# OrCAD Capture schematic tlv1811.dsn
size A
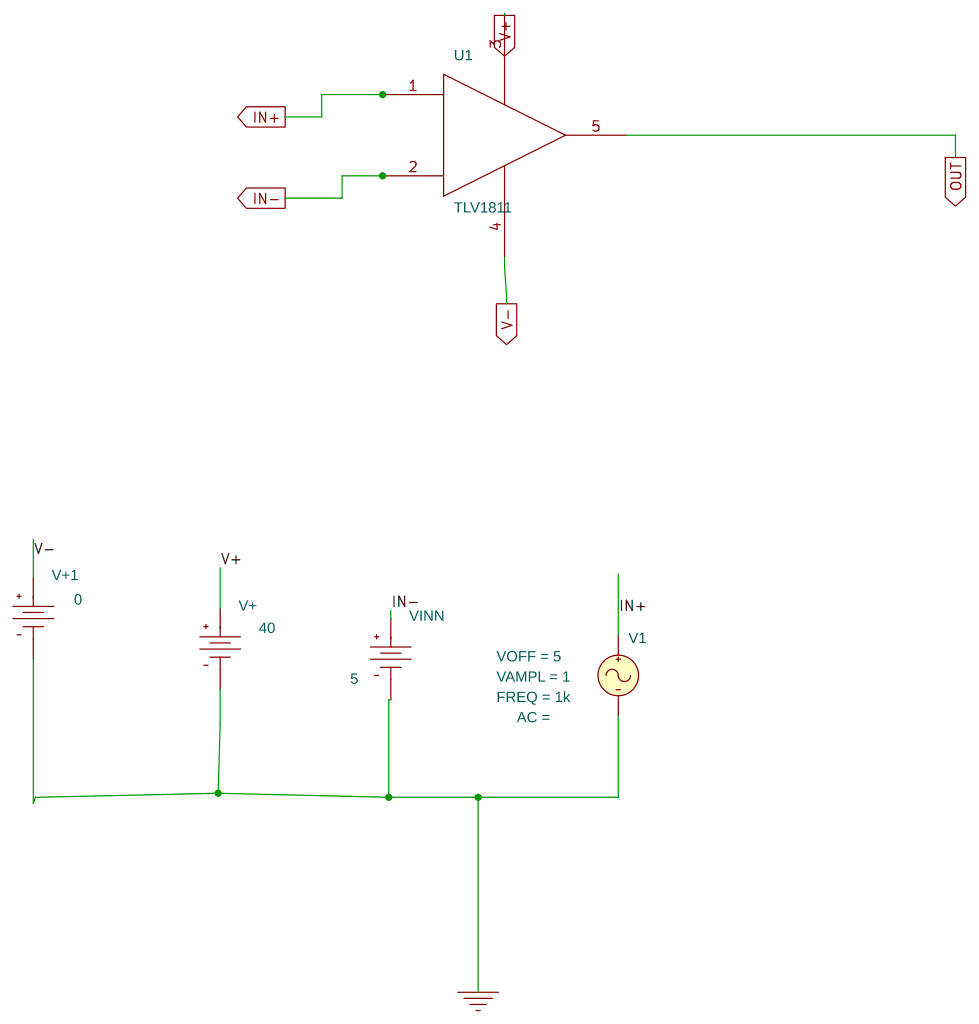
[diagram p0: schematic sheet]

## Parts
U1  TLV1811
V1  VSIN
V+  VDC
V+1  VDC
VINN  VDC

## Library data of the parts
U1 = TLV1811
V1 = VSIN: FREQ: 1k; VAMPL: 1; VOFF: 5
V+ = VDC: DC: 40
V+1 = VDC: DC: 0
VINN = VDC: DC: 5

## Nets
0: V1.2(-) V+.1(-) V+1.1(-) VINN.1(-)
IN+: U1.1(IN+) V1.1(+)
IN-: U1.2(IN-) VINN.0(+)
OUT: U1.5(OUT)
V+: U1.3(V+) V+.0(+)
V-: U1.4(V-) V+1.0(+)
